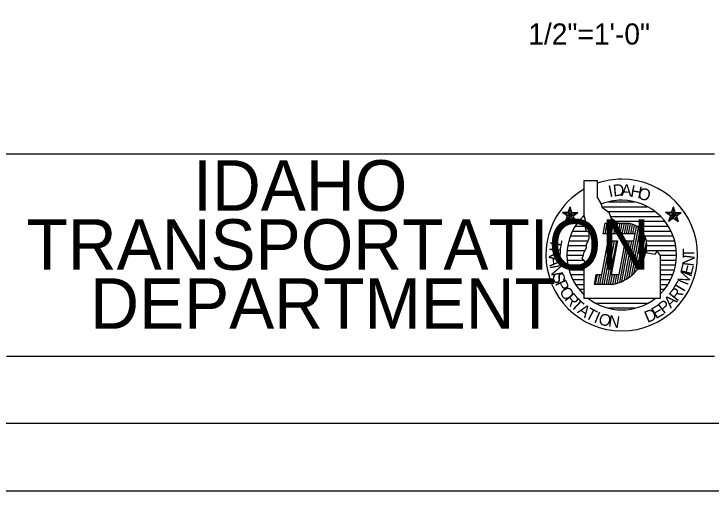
# Model space of a CAD drawing. Extents: x 0 to 68, y 0 to 47.1.
# Drawn here: x 28.11 to 38.45, y 0 to 7.08 of the extents above; entities that cross this region are included whole.
import ezdxf

# ---------------------------------------------------------------- set-up
doc = ezdxf.new("R2010")
doc.units = 0
for name, color, linetype in [('BORDER_ANNO_Cutsheet', 7, 'Continuous'), ('BRDG_ANNO_Anno-Sheet', 7, 'Continuous'), ('BRDG_ANNO_General-Notes', 7, 'Continuous')]:
    doc.layers.add(name, color=color, linetype=linetype)

msp = doc.modelspace()

# ---------------------------------------------------------------- linework, layer by layer
at = {"layer": 'BORDER_ANNO_Cutsheet'}
msp.add_lwpolyline([(0, 44), (68, 44), (68, 0), (0, 0)], close=True, dxfattribs=at)
at = {"layer": 'BRDG_ANNO_Anno-Sheet'}
for p, q in [((3, 5), (38.5, 5)), ((36.569, 4.085), (36.569, 4.606)), ((36.569, 4.606), (36.766, 4.606)), ((36.766, 4.346), (36.766, 4.606)), ((36.766, 4.346), (36.819, 4.252)), ((36.819, 4.252), (36.829, 4.21)), ((36.93, 4.289), (37.316, 4.289)), ((36.331, 4.131), (36.359, 4.214)), ((36.359, 4.047), (36.359, 4.214)), ((36.386, 4.131), (36.359, 4.214)), ((36.829, 4.21), (36.932, 4.138)), ((36.834, 4.216), (37.501, 4.216)), ((36.93, 4.145), (37.614, 4.145)), ((36.932, 4.138), (36.965, 4.054)), ((37.864, 4.131), (37.891, 4.214)), ((37.891, 4.047), (37.891, 4.214)), ((37.919, 4.131), (37.891, 4.214)), ((36.402, 4.08), (36.245, 4.131)), ((36.331, 4.131), (36.245, 4.131)), ((36.315, 4.08), (36.245, 4.131)), ((36.386, 4.131), (36.288, 3.996)), ((36.315, 4.08), (36.288, 3.996)), ((36.359, 4.047), (36.288, 3.996)), ((36.315, 4.08), (36.474, 4.131)), ((36.331, 4.131), (36.43, 3.996)), ((36.359, 4.047), (36.43, 3.996)), ((36.386, 4.131), (36.474, 4.131)), ((36.402, 4.08), (36.474, 4.131)), ((36.402, 4.08), (36.43, 3.996)), ((36.549, 4.072), (36.572, 4.072)), ((36.589, 4.013), (36.569, 4.085)), ((36.957, 4.072), (37.701, 4.072)), ((36.965, 4.054), (37.069, 3.971)), ((37.935, 4.08), (37.776, 4.131)), ((37.847, 4.08), (37.776, 4.131)), ((37.864, 4.131), (37.776, 4.131)), ((37.919, 4.131), (37.82, 3.996)), ((37.847, 4.08), (37.82, 3.996)), ((37.891, 4.047), (37.82, 3.996)), ((37.847, 4.08), (38.005, 4.131)), ((37.864, 4.131), (37.962, 3.996)), ((37.891, 4.047), (37.962, 3.996)), ((37.919, 4.131), (38.005, 4.131)), ((37.935, 4.08), (38.005, 4.131)), ((37.935, 4.08), (37.962, 3.996)), ((36.484, 4.001), (36.587, 4.001)), ((36.589, 3.95), (36.589, 4.013)), ((36.589, 3.897), (36.589, 3.95)), ((36.85, 3.814), (36.881, 3.971)), ((36.879, 3.814), (36.907, 3.971)), ((36.881, 3.971), (37.225, 3.971)), ((36.91, 3.814), (36.94, 3.971)), ((36.942, 3.814), (36.971, 3.971)), ((36.974, 3.814), (37.004, 3.971)), ((37.005, 3.814), (37.035, 3.971)), ((37.031, 4.001), (37.765, 4.001)), ((37.038, 3.814), (37.066, 3.971)), ((37.069, 3.814), (37.099, 3.971)), ((37.101, 3.814), (37.13, 3.971)), ((37.133, 3.814), (37.163, 3.971)), ((37.165, 3.814), (37.194, 3.971)), ((37.196, 3.814), (37.226, 3.971)), ((37.227, 3.814), (37.256, 3.962)), ((37.26, 3.814), (37.286, 3.954)), ((37.291, 3.814), (37.315, 3.94)), ((36.394, 3.856), (36.596, 3.856)), ((36.434, 3.929), (36.585, 3.929)), ((36.6, 3.856), (36.589, 3.897)), ((36.641, 3.835), (36.6, 3.856)), ((36.641, 3.782), (36.641, 3.835)), ((37.199, 3.149), (37.344, 3.924)), ((37.235, 3.171), (37.373, 3.904)), ((37.273, 3.201), (37.399, 3.877)), ((37.311, 3.237), (37.425, 3.849)), ((37.337, 3.929), (37.815, 3.929)), ((37.42, 3.856), (37.855, 3.856)), ((36.362, 3.785), (36.637, 3.785)), ((36.62, 3.7), (36.641, 3.751)), ((36.641, 3.751), (36.641, 3.782)), ((37.322, 3.814), (36.85, 3.814)), ((37.304, 3.71), (37.322, 3.814)), ((37.351, 3.28), (37.45, 3.812)), ((37.394, 3.337), (37.474, 3.764)), ((37.465, 3.785), (37.886, 3.785)), ((36.325, 3.641), (36.596, 3.641)), ((36.341, 3.712), (36.623, 3.712)), ((36.6, 3.657), (36.62, 3.7)), ((36.6, 3.606), (36.6, 3.657)), ((36.829, 3.21), (36.922, 3.71)), ((36.832, 3.064), (36.954, 3.71)), ((36.865, 3.064), (36.986, 3.71)), ((36.896, 3.064), (37.017, 3.71)), ((36.922, 3.71), (37.06, 3.71)), ((36.929, 3.064), (37.05, 3.71)), ((37.06, 3.71), (36.966, 3.21)), ((37.087, 3.21), (37.181, 3.71)), ((37.094, 3.095), (37.209, 3.71)), ((37.127, 3.11), (37.24, 3.71)), ((37.163, 3.126), (37.273, 3.71)), ((37.181, 3.71), (37.304, 3.71)), ((37.444, 3.435), (37.491, 3.69)), ((37.489, 3.712), (37.909, 3.712)), ((37.495, 3.641), (37.925, 3.641)), ((36.315, 3.569), (36.581, 3.569)), ((36.557, 3.501), (36.569, 3.544)), ((36.569, 3.544), (36.6, 3.606)), ((37.481, 3.555), (37.496, 3.532)), ((37.485, 3.569), (37.935, 3.569)), ((37.496, 3.532), (37.559, 3.522)), ((37.559, 3.522), (37.621, 3.512)), ((37.621, 3.512), (37.652, 3.554)), ((37.652, 3.554), (37.694, 3.491)), ((36.312, 3.496), (36.555, 3.496)), ((36.316, 3.425), (36.562, 3.425)), ((36.538, 3.45), (36.557, 3.501)), ((36.569, 3.419), (36.538, 3.45)), ((36.589, 3.387), (36.569, 3.419)), ((37.69, 3.496), (37.938, 3.496)), ((37.694, 3.491), (37.694, 2.855)), ((37.695, 3.425), (37.934, 3.425)), ((36.326, 3.353), (36.596, 3.353)), ((36.569, 3.304), (36.6, 3.335)), ((36.6, 3.366), (36.589, 3.387)), ((36.6, 3.335), (36.6, 3.366)), ((37.694, 3.353), (37.924, 3.353)), ((36.343, 3.281), (36.567, 3.281)), ((36.367, 3.209), (36.565, 3.209)), ((36.569, 2.855), (36.569, 3.304)), ((36.719, 3.064), (36.746, 3.21)), ((36.737, 3.064), (36.765, 3.21)), ((36.746, 3.21), (36.829, 3.21)), ((36.77, 3.064), (36.797, 3.21)), ((36.801, 3.064), (36.829, 3.21)), ((36.96, 3.064), (36.987, 3.21)), ((36.966, 3.21), (37.087, 3.21)), ((36.992, 3.065), (37.02, 3.21)), ((37.026, 3.074), (37.051, 3.21)), ((37.06, 3.084), (37.082, 3.21)), ((37.694, 3.281), (37.907, 3.281)), ((37.694, 3.209), (37.883, 3.209)), ((36.399, 3.136), (36.565, 3.136)), ((37.694, 3.136), (37.85, 3.136)), ((36.44, 3.065), (36.566, 3.065)), ((36.985, 3.064), (36.719, 3.064)), ((37.694, 3.065), (37.81, 3.065)), ((36.491, 2.992), (36.565, 2.992)), ((36.555, 2.921), (36.567, 2.921)), ((37.694, 2.992), (37.76, 2.992)), ((37.694, 2.855), (36.569, 2.855)), ((37.501, 2.782), (36.744, 2.782)), ((37.317, 2.711), (36.935, 2.711)), ((28, 2), (38.5, 2))]:
    msp.add_line(p, q, dxfattribs=at)
msp.add_lwpolyline([(3, 43), (67, 43), (67, 1), (3, 1)], close=True, dxfattribs=at)
for centre, radius, start, end in [((37.125, 3.5), 1.125, 90, 108.596), ((37.125, 3.5), 1.125, 0, 90), ((37.125, 3.5), 1.125, 119.6331, 180), ((37.125, 3.5), 0.813, 90, 112.1452), ((37.125, 3.5), 0.813, 0, 90), ((37.125, 3.5), 0.813, 133.1926, 180), ((37.167, 3.648), 0.328, 343.4981, 79.7362), ((36.87, 3.676), 0.623, 280.6479, 348.7719), ((37.125, 3.5), 1.125, 180, 270), ((37.125, 3.5), 0.813, 180.2644, 226.7946), ((37.125, 3.5), 1.125, 270, 0), ((37.125, 3.5), 0.813, 314.427, 0), ((37.125, 3.5), 0.813, 232.5658, 270), ((37.125, 3.5), 0.813, 270, 307.4536)]:
    msp.add_arc(centre, radius, start, end, dxfattribs=at)

# ---------------------------------------------------------------- texts
for s, p in [('IDAHO', (30.767, 4.156)), ('TRANSPORTATION', (28.294, 3.281)), ('DEPARTMENT', (29.239, 2.406))]:
    msp.add_text(s, height=0.75, dxfattribs=at).set_placement(p)
for s, rotation, p in [('D', 5.2118, (37.002, 4.369)), ('I', 11.9519, (36.944, 4.356)), ('A', 357.8718, (37.114, 4.376)), ('H', 349.6318, (37.244, 4.367)), ('O', 342.1917, (37.349, 4.346)), ('T', 259.4265, (36.076, 3.751)), ('R', 266.0275, (36.053, 3.615)), ('T', 90.4926, (38.204, 3.459)), ('A', 273.764, (36.046, 3.481)), ('N', 83.1932, (38.19, 3.326)), ('N', 280.3758, (36.057, 3.342)), ('E', 75.6105, (38.159, 3.194)), ('S', 287.9279, (36.086, 3.208)), ('M', 67.7139, (38.101, 3.041)), ('P', 295.4976, (36.131, 3.081)), ('T', 59.0362, (38.027, 2.91)), ('O', 302.6446, (36.191, 2.96)), ('R', 52.3344, (37.947, 2.802)), ('R', 309.9079, (36.267, 2.845)), ('T', 317.1211, (36.355, 2.742)), ('P', 37.6656, (37.746, 2.619)), ('A', 45, (37.851, 2.701)), ('A', 324.6375, (36.456, 2.651)), ('T', 331.7503, (36.569, 2.574)), ('D', 22.9887, (37.506, 2.491)), ('E', 30.5476, (37.631, 2.547)), ('I', 337.0213, (36.699, 2.507)), ('O', 343.3287, (36.765, 2.481)), ('N', 351.6598, (36.917, 2.44))]:
    msp.add_text(s, height=0.174, rotation=rotation, dxfattribs=at).set_placement(p)
at = {"layer": 'BRDG_ANNO_General-Notes'}
msp.add_text('1/2"=1\'-0"', height=0.3125, dxfattribs=at).set_placement((35.738, 6.622))

doc.saveas('drawing.dxf')
